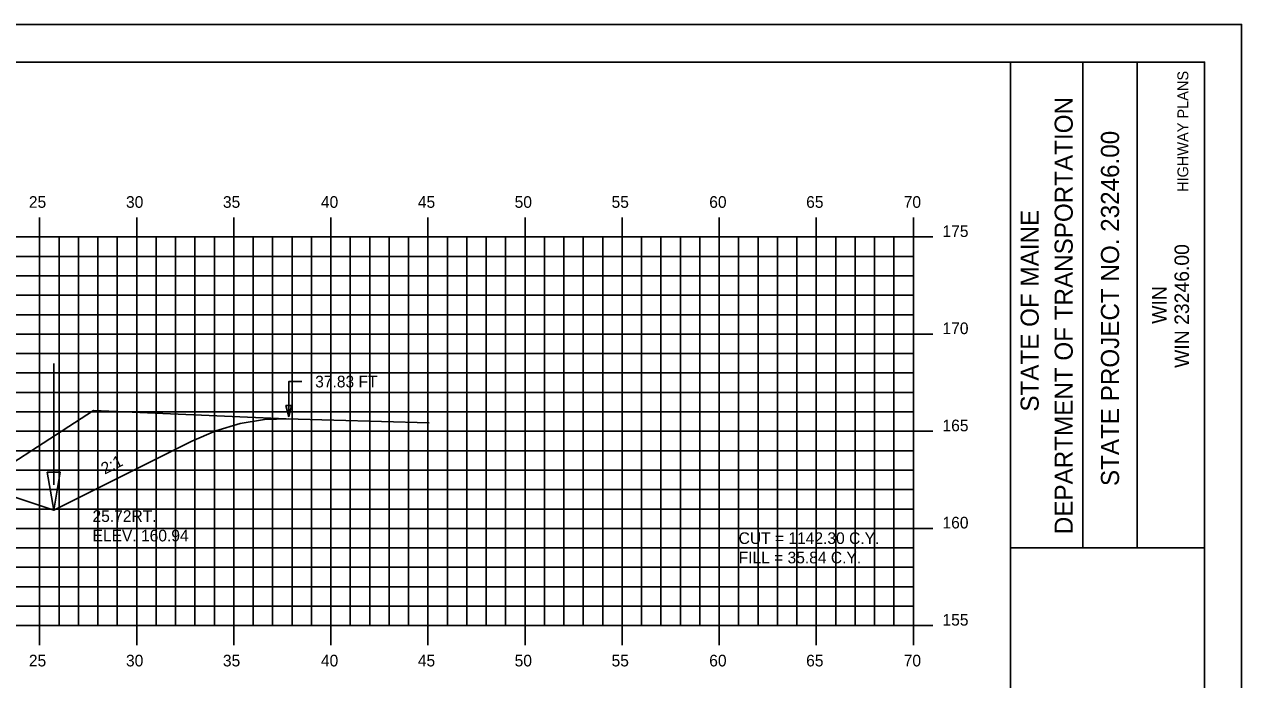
# Model space of a CAD drawing. Extents: x 1141424 to 1141594, y 608981 to 609091.
# Drawn here: x 1141531.5 to 1141594.2, y 609057.6 to 609091.3 of the extents above; entities that cross this region are included whole.
import ezdxf

# ---------------------------------------------------------------- set-up
doc = ezdxf.new("R2010")
doc.units = 0
for name, color, linetype in [('ANNOTATION', 7, 'Continuous'), ('BORDER', 7, 'Continuous'), ('D_Drainage_Ditch_Line', 7, 'Continuous'), ('D_Roadway_SlopeLines', 7, 'Continuous'), ('D_Text_Standard', 7, 'Continuous'), ('H_V ANNOTATION', 7, 'Continuous'), ('HIGHWAY_TITLE', 7, 'Continuous'), ('MAJOR', 7, 'Continuous'), ('MINOR', 7, 'Continuous'), ('PLOT BOUNDARY', 7, 'Continuous'), ('S_Roadway_Centerline', 7, 'Continuous')]:
    doc.layers.add(name, color=color, linetype=linetype)

msp = doc.modelspace()

# ---------------------------------------------------------------- linework, layer by layer
msp.add_lwpolyline([(1141456.146, 609073.465), (1141457.396, 609073.337), (1141458.646, 609073.068), (1141459.896, 609072.656), (1141461.146, 609072.102), (1141473.145, 609066.102), (1141476.145, 609067.102), (1141483.295, 609069.486), (1141483.296, 609069.486), (1141496.271, 609070.005), (1141507.271, 609070.225), (1141518.271, 609070.005), (1141522.271, 609069.845), (1141529.994, 609067.271), (1141532.994, 609066.271), (1141540.103, 609069.825), (1141541.353, 609070.365), (1141542.603, 609070.736), (1141543.853, 609070.937), (1141545.103, 609070.968)])
at = {"layer": 'BORDER'}
for p, q in [((1141582.271, 608984.335), (1141582.271, 609089.335)), ((1141585.999, 609064.332), (1141585.999, 609089.332)), ((1141588.795, 609064.332), (1141588.795, 609089.332)), ((1141582.272, 609064.329), (1141592.271, 609064.329))]:
    msp.add_line(p, q, dxfattribs=at)
msp.add_lwpolyline([(1141432.271, 608984.335), (1141592.271, 608984.335), (1141592.271, 609089.335), (1141432.271, 609089.335)], close=True, dxfattribs=at)
at = {"layer": 'D_Drainage_Ditch_Line'}
msp.add_line((1141532.994, 609067.583), (1141532.995, 609073.826), dxfattribs=at)
msp.add_line((1141532.994, 609067.583), (1141532.995, 609073.826), dxfattribs=at)
msp.add_lwpolyline([(1141532.666, 609068.239), (1141533.322, 609068.239), (1141532.994, 609066.271)], close=True, dxfattribs=at)
msp.add_lwpolyline([(1141532.666, 609068.239), (1141533.322, 609068.239), (1141532.994, 609066.271)], close=True, dxfattribs=at)
at = {"layer": 'D_Roadway_SlopeLines'}
for points in [[(1141532.994, 609066.271), (1141540.103, 609069.825), (1141541.353, 609070.365), (1141542.603, 609070.736), (1141543.853, 609070.937), (1141545.103, 609070.968)], [(1141529.994, 609067.271), (1141532.994, 609066.271)]]:
    msp.add_lwpolyline(points, dxfattribs=at)
at = {"layer": 'D_Text_Standard'}
msp.add_lwpolyline([(1141545.103, 609071.075), (1141545.103, 609072.892), (1141545.783, 609072.892)], dxfattribs=at)
msp.add_lwpolyline([(1141545.103, 609071.075), (1141544.957, 609071.657), (1141545.248, 609071.657)], close=True, dxfattribs=at)
at = {"layer": 'MAJOR'}
for p, q in [((1141532.271, 609081.337), (1141532.271, 609080.335)), ((1141537.271, 609081.337), (1141537.271, 609080.335)), ((1141542.271, 609081.337), (1141542.271, 609080.335)), ((1141547.271, 609081.337), (1141547.271, 609080.335)), ((1141552.271, 609081.337), (1141552.271, 609080.335)), ((1141557.271, 609081.337), (1141557.271, 609080.335)), ((1141562.271, 609081.337), (1141562.271, 609080.335)), ((1141567.271, 609081.337), (1141567.271, 609080.335)), ((1141572.271, 609081.337), (1141572.271, 609080.335)), ((1141577.271, 609081.337), (1141577.271, 609080.335)), ((1141437.271, 609080.335), (1141577.271, 609080.335)), ((1141437.271, 609080.335), (1141577.271, 609080.335)), ((1141532.271, 609060.335), (1141532.271, 609080.335)), ((1141537.271, 609060.335), (1141537.271, 609080.335)), ((1141542.271, 609060.335), (1141542.271, 609080.335)), ((1141547.271, 609060.335), (1141547.271, 609080.335)), ((1141552.271, 609060.335), (1141552.271, 609080.335)), ((1141557.271, 609060.335), (1141557.271, 609080.335)), ((1141562.271, 609060.335), (1141562.271, 609080.335)), ((1141567.271, 609060.335), (1141567.271, 609080.335)), ((1141572.271, 609060.335), (1141572.271, 609080.335)), ((1141578.273, 609080.335), (1141576.269, 609080.335)), ((1141577.271, 609060.335), (1141577.271, 609080.335)), ((1141577.271, 609060.335), (1141577.271, 609080.335)), ((1141437.271, 609075.335), (1141577.271, 609075.335)), ((1141578.273, 609075.335), (1141576.269, 609075.335)), ((1141437.271, 609070.335), (1141577.271, 609070.335)), ((1141578.273, 609070.335), (1141576.269, 609070.335)), ((1141437.271, 609065.335), (1141577.271, 609065.335)), ((1141578.273, 609065.335), (1141576.269, 609065.335)), ((1141437.271, 609060.335), (1141577.271, 609060.335)), ((1141437.271, 609060.335), (1141577.271, 609060.335)), ((1141532.271, 609059.333), (1141532.271, 609060.335)), ((1141537.271, 609059.333), (1141537.271, 609060.335)), ((1141542.271, 609059.333), (1141542.271, 609060.335)), ((1141547.271, 609059.333), (1141547.271, 609060.335)), ((1141552.271, 609059.333), (1141552.271, 609060.335)), ((1141557.271, 609059.333), (1141557.271, 609060.335)), ((1141562.271, 609059.333), (1141562.271, 609060.335)), ((1141567.271, 609059.333), (1141567.271, 609060.335)), ((1141572.271, 609059.333), (1141572.271, 609060.335)), ((1141578.273, 609060.335), (1141576.269, 609060.335)), ((1141577.271, 609059.333), (1141577.271, 609060.335))]:
    msp.add_line(p, q, dxfattribs=at)
at = {"layer": 'MINOR'}
for p, q in [((1141533.271, 609060.335), (1141533.271, 609080.335)), ((1141534.271, 609060.335), (1141534.271, 609080.335)), ((1141535.271, 609060.335), (1141535.271, 609080.335)), ((1141536.271, 609060.335), (1141536.271, 609080.335)), ((1141538.271, 609060.335), (1141538.271, 609080.335)), ((1141539.271, 609060.335), (1141539.271, 609080.335)), ((1141540.271, 609060.335), (1141540.271, 609080.335)), ((1141541.271, 609060.335), (1141541.271, 609080.335)), ((1141543.271, 609060.335), (1141543.271, 609080.335)), ((1141544.271, 609060.335), (1141544.271, 609080.335)), ((1141545.271, 609060.335), (1141545.271, 609080.335)), ((1141546.271, 609060.335), (1141546.271, 609080.335)), ((1141548.271, 609060.335), (1141548.271, 609080.335)), ((1141549.271, 609060.335), (1141549.271, 609080.335)), ((1141550.271, 609060.335), (1141550.271, 609080.335)), ((1141551.271, 609060.335), (1141551.271, 609080.335)), ((1141553.271, 609060.335), (1141553.271, 609080.335)), ((1141554.271, 609060.335), (1141554.271, 609080.335)), ((1141555.271, 609060.335), (1141555.271, 609080.335)), ((1141556.271, 609060.335), (1141556.271, 609080.335)), ((1141558.271, 609060.335), (1141558.271, 609080.335)), ((1141559.271, 609060.335), (1141559.271, 609080.335)), ((1141560.271, 609060.335), (1141560.271, 609080.335)), ((1141561.271, 609060.335), (1141561.271, 609080.335)), ((1141563.271, 609060.335), (1141563.271, 609080.335)), ((1141564.271, 609060.335), (1141564.271, 609080.335)), ((1141565.271, 609060.335), (1141565.271, 609080.335)), ((1141566.271, 609060.335), (1141566.271, 609080.335)), ((1141568.271, 609060.335), (1141568.271, 609080.335)), ((1141569.271, 609060.335), (1141569.271, 609080.335)), ((1141570.271, 609060.335), (1141570.271, 609080.335)), ((1141571.271, 609060.335), (1141571.271, 609080.335)), ((1141573.271, 609060.335), (1141573.271, 609080.335)), ((1141574.271, 609060.335), (1141574.271, 609080.335)), ((1141575.271, 609060.335), (1141575.271, 609080.335)), ((1141576.271, 609060.335), (1141576.271, 609080.335)), ((1141437.271, 609079.335), (1141577.271, 609079.335)), ((1141577.271, 609079.335), (1141576.269, 609079.335)), ((1141437.271, 609078.335), (1141577.271, 609078.335)), ((1141577.271, 609078.335), (1141576.269, 609078.335)), ((1141437.271, 609077.335), (1141577.271, 609077.335)), ((1141577.271, 609077.335), (1141576.269, 609077.335)), ((1141437.271, 609076.335), (1141577.271, 609076.335)), ((1141577.271, 609076.335), (1141576.269, 609076.335)), ((1141437.271, 609074.335), (1141577.271, 609074.335)), ((1141577.271, 609074.335), (1141576.269, 609074.335)), ((1141437.271, 609073.335), (1141577.271, 609073.335)), ((1141577.271, 609073.335), (1141576.269, 609073.335)), ((1141437.271, 609072.335), (1141577.271, 609072.335)), ((1141577.271, 609072.335), (1141576.269, 609072.335)), ((1141437.271, 609071.335), (1141577.271, 609071.335)), ((1141577.271, 609071.335), (1141576.269, 609071.335)), ((1141437.271, 609069.335), (1141577.271, 609069.335)), ((1141577.271, 609069.335), (1141576.269, 609069.335)), ((1141437.271, 609068.335), (1141577.271, 609068.335)), ((1141577.271, 609068.335), (1141576.269, 609068.335)), ((1141437.271, 609067.335), (1141577.271, 609067.335)), ((1141577.271, 609067.335), (1141576.269, 609067.335)), ((1141437.271, 609066.335), (1141577.271, 609066.335)), ((1141577.271, 609066.335), (1141576.269, 609066.335)), ((1141437.271, 609064.335), (1141577.271, 609064.335)), ((1141577.271, 609064.335), (1141576.269, 609064.335)), ((1141437.271, 609063.335), (1141577.271, 609063.335)), ((1141577.271, 609063.335), (1141576.269, 609063.335)), ((1141437.271, 609062.335), (1141577.271, 609062.335)), ((1141577.271, 609062.335), (1141576.269, 609062.335)), ((1141437.271, 609061.335), (1141577.271, 609061.335)), ((1141577.271, 609061.335), (1141576.269, 609061.335))]:
    msp.add_line(p, q, dxfattribs=at)
at = {"layer": 'PLOT BOUNDARY'}
msp.add_lwpolyline([(1141424.178, 608981.276), (1141594.178, 608981.276), (1141594.178, 609091.276), (1141424.178, 609091.276)], close=True, dxfattribs=at)
at = {"layer": 'S_Roadway_Centerline'}
msp.add_lwpolyline([(1141454.537, 609073.535), (1141458.051, 609073.382), (1141478.858, 609072.336), (1141491.012, 609067.255), (1141491.392, 609067.105), (1141495.226, 609067.794), (1141495.325, 609067.825), (1141495.441, 609067.836), (1141498.174, 609068.166), (1141509.012, 609068.453), (1141509.602, 609068.468), (1141519.951, 609068.08), (1141520.424, 609068.064), (1141520.58, 609068.047), (1141523.884, 609067.752), (1141523.972, 609067.719), (1141527.544, 609066.625), (1141527.941, 609066.801), (1141535.037, 609071.404), (1141544.971, 609070.972), (1141552.331, 609070.764)], dxfattribs=at)

# ---------------------------------------------------------------- texts
at = {"layer": 'ANNOTATION'}
msp.add_text('2:1', height=0.6, rotation=26.56505, dxfattribs=at).set_placement((1141535.621, 609068.102))
at = {"layer": 'BORDER'}
for s, height, p in [('DEPARTMENT OF TRANSPORTATION', 0.93176, (1141585.478, 609065.041)), ('STATE PROJECT NO. 23246.00', 0.93176, (1141587.863, 609067.517)), ('STATE OF MAINE', 0.93176, (1141583.726, 609071.347)), ('WIN 23246.00', 0.74527, (1141591.466, 609073.596)), ('WIN', 0.7453, (1141590.308, 609075.865))]:
    msp.add_text(s, height=height, rotation=90, dxfattribs=at).set_placement(p)
at = {"layer": 'D_Text_Standard'}
for s, p in [('37.83 FT', (1141546.463, 609072.592)), ('25.72', (1141534.994, 609065.671)), ('25.72RT.', (1141534.994, 609065.671)), ('ELEV. 160.94', (1141534.994, 609064.669)), ('ELEV. 160.94', (1141534.994, 609064.669)), ('CUT = 1142.30 C.Y.', (1141568.271, 609064.535)), ('FILL = 35.84 C.Y.', (1141568.271, 609063.539))]:
    msp.add_text(s, height=0.6, dxfattribs=at).set_placement(p)
at = {"layer": 'H_V ANNOTATION'}
for s, p in [('25', (1141531.717, 609081.835)), ('30', (1141536.719, 609081.835)), ('35', (1141541.711, 609081.835)), ('40', (1141546.757, 609081.835)), ('45', (1141551.749, 609081.835)), ('50', (1141556.735, 609081.835)), ('55', (1141561.727, 609081.835)), ('60', (1141566.757, 609081.835)), ('65', (1141571.749, 609081.835)), ('70', (1141576.773, 609081.835)), ('175', (1141578.771, 609080.335)), ('170', (1141578.771, 609075.335)), ('165', (1141578.771, 609070.335)), ('160', (1141578.771, 609065.335)), ('155', (1141578.771, 609060.335)), ('25', (1141531.717, 609058.235)), ('30', (1141536.719, 609058.235)), ('35', (1141541.711, 609058.235)), ('40', (1141546.757, 609058.235)), ('45', (1141551.749, 609058.235)), ('50', (1141556.735, 609058.235)), ('55', (1141561.727, 609058.235)), ('60', (1141566.757, 609058.235)), ('65', (1141571.749, 609058.235)), ('70', (1141576.773, 609058.235))]:
    msp.add_text(s, height=0.6, dxfattribs=at).set_placement(p)
at = {"layer": 'HIGHWAY_TITLE'}
msp.add_text('HIGHWAY PLANS', height=0.55901, rotation=90, dxfattribs=at).set_placement((1141591.429, 609082.65))

doc.saveas('drawing.dxf')
